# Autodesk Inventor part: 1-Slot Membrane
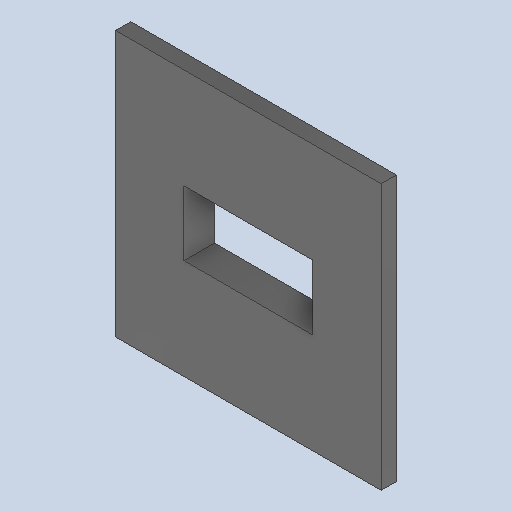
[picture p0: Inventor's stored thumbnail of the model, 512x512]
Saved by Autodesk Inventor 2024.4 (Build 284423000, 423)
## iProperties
Created: 2025-08
Part Number: 1-Slot Membrane
Material: Generic
Document SubType Name: Modeling
Designer: AdminForWorker
Density: 1 g/cm^3
Appearance: Default
Title: 1-Slot Membrane
Author: AdminForWorker
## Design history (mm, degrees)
feature "Body1"
body "Solid1"
